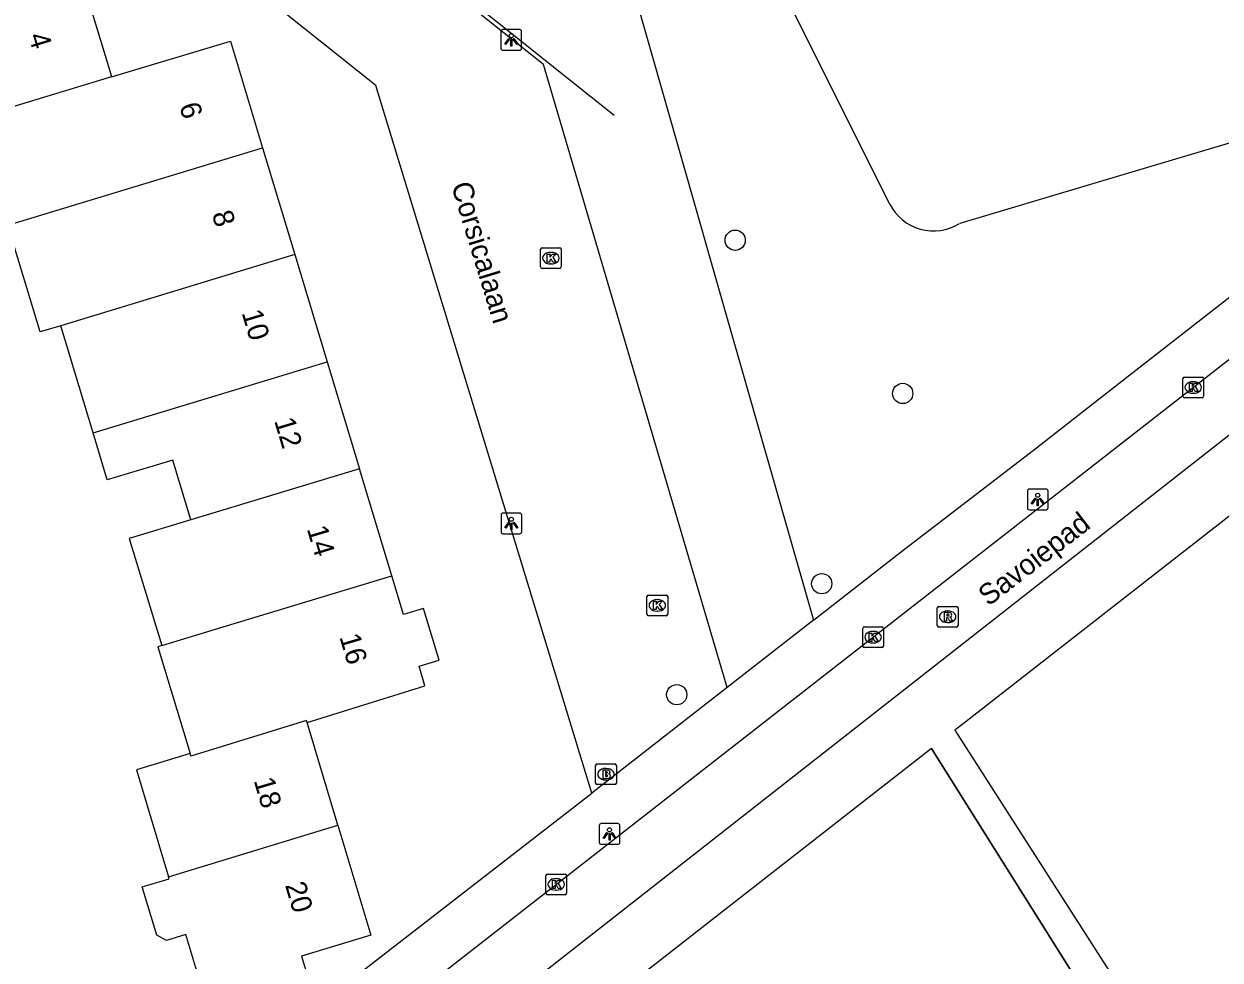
# Model space of a CAD drawing. Extents: x 157767 to 159171, y 387842 to 389425.
# Drawn here: x 158542.4 to 158600.2, y 388420.3 to 388465.6 of the extents above; entities that cross this region are included whole.
import ezdxf

# ---------------------------------------------------------------- set-up
doc = ezdxf.new("R2010")
doc.units = 0
for name, color, linetype in [('IMGEO_Boom', 7, 'Continuous'), ('IMGEO_Brandkraan', 7, 'Continuous'), ('IMGEO_Fietspad_gesloten', 7, 'Continuous'), ('IMGEO_Hek', 7, 'Continuous'), ('IMGEO_Kolk', 7, 'Continuous'), ('IMGEO_Lichtpunt', 7, 'Continuous'), ('IMGEO_Muur', 7, 'Continuous'), ('IMGEO_Openbare_ruimte_label', 7, 'Continuous'), ('IMGEO_Pand', 7, 'Continuous'), ('IMGEO_Pand_nummerreeks', 7, 'Continuous'), ('IMGEO_Parkeervlak_open', 7, 'Continuous'), ('IMGEO_Rijbaan_lokaal_open', 7, 'Continuous'), ('IMGEO_Rioolput', 7, 'Continuous'), ('IMGEO_Voetpad_open', 7, 'Continuous')]:
    doc.layers.add(name, color=color, linetype=linetype)

msp = doc.modelspace()

# ---------------------------------------------------------------- linework, layer by layer
at = {"layer": 'IMGEO_Boom'}
for centre in [(158576.807, 388455.106), (158584.898, 388447.704), (158580.987, 388438.512), (158573.98, 388433.149)]:
    msp.add_circle(centre, 0.489, dxfattribs=at)
at = {"layer": 'IMGEO_Brandkraan'}
for p, q in [((158570.065, 388428.879), (158570.065, 388429.731)), ((158570.14, 388429.805), (158570.992, 388429.805)), ((158571.066, 388429.731), (158571.066, 388428.879)), ((158570.553, 388429.585), (158570.578, 388429.585)), ((158570.992, 388428.805), (158570.14, 388428.805)), ((158570.576, 388429.025), (158570.551, 388429.025))]:
    msp.add_line(p, q, dxfattribs=at)
for points in [[(158570.065, 388428.879), (158570.065, 388429.731)], [(158570.14, 388429.805), (158570.992, 388429.805)], [(158571.066, 388429.731), (158571.066, 388428.879)], [(158570.413, 388429.505), (158570.413, 388429.105), (158570.626, 388429.105)], [(158570.644, 388429.505), (158570.413, 388429.505)], [(158570.592, 388429.424), (158570.538, 388429.424), (158570.538, 388429.348)], [(158570.538, 388429.348), (158570.591, 388429.348)], [(158570.6, 388429.272), (158570.538, 388429.272), (158570.538, 388429.191)], [(158570.538, 388429.191), (158570.6, 388429.191)], [(158570.992, 388428.805), (158570.14, 388428.805)]]:
    msp.add_lwpolyline(points, dxfattribs=at)
for centre, radius, start, end in [((158570.142, 388429.729), 0.0765, 91.55205, 178.44795), ((158570.142, 388429.729), 0.0765, 91.55205, 178.44795), ((158570.99, 388429.729), 0.0765, 1.55205, 88.44795), ((158570.99, 388429.729), 0.0765, 1.55205, 88.44795), ((158570.593, 388429.386), 0.0379, 267.82845, 90.93552), ((158570.601, 388429.231), 0.0404, 269.87594, 90.50774), ((158570.648, 388429.36), 0.145, 59.4692, 91.53667), ((158570.673, 388429.407), 0.0922, 285.51372, 58.15012), ((158570.678, 388429.215), 0.105, 301.31148, 78.98903), ((158570.142, 388428.881), 0.0765, 181.55205, 268.44795), ((158570.142, 388428.881), 0.0765, 181.55205, 268.44795), ((158570.632, 388429.356), 0.251, 268.66757, 293.53466), ((158570.99, 388428.881), 0.0765, 271.55205, 358.44795), ((158570.99, 388428.881), 0.0765, 271.55205, 358.44795)]:
    msp.add_arc(centre, radius, start, end, dxfattribs=at)
for centre, major_axis, ratio, start_param, end_param in [((158570.552, 388429.305), (-0.387, 0.002), 0.722429, 4.712389, 7.853982), ((158570.577, 388429.305), (-0.39, 0.002), 0.717154, 1.570796, 4.712389)]:
    msp.add_ellipse(centre, major_axis=major_axis, ratio=ratio, start_param=start_param, end_param=end_param, dxfattribs=at)
at = {"layer": 'IMGEO_Fietspad_gesloten'}
for points in [[(158612.35, 388454.746), (158604.077, 388448.361), (158556.877, 388411.353), (158545.756, 388402.727), (158544.054, 388401.469), (158540.023, 388398.619), (158533.491, 388394.369), (158520.642, 388386.656)], [(158543.134, 388404.513), (158547.311, 388407.72), (158607.672, 388454.811)]]:
    msp.add_lwpolyline(points, dxfattribs=at)
at = {"layer": 'IMGEO_Hek'}
msp.add_lwpolyline([(158570.958, 388461.13), (158542.949, 388483.478)], dxfattribs=at)
at = {"layer": 'IMGEO_Kolk'}
for p, q in [((158567.404, 388453.814), (158567.404, 388454.666)), ((158567.479, 388454.74), (158568.331, 388454.74)), ((158568.405, 388454.666), (158568.405, 388453.814)), ((158567.892, 388454.52), (158567.917, 388454.52)), ((158568.331, 388453.74), (158567.479, 388453.74)), ((158567.915, 388453.96), (158567.89, 388453.96)), ((158598.433, 388447.566), (158598.433, 388448.418)), ((158598.508, 388448.492), (158599.36, 388448.492)), ((158598.921, 388448.272), (158598.946, 388448.272)), ((158599.434, 388448.418), (158599.434, 388447.566)), ((158598.944, 388447.712), (158598.919, 388447.712)), ((158599.36, 388447.492), (158598.508, 388447.492)), ((158572.545, 388437.037), (158572.545, 388437.889)), ((158572.62, 388437.963), (158573.472, 388437.963)), ((158573.546, 388437.889), (158573.546, 388437.037)), ((158573.033, 388437.743), (158573.058, 388437.743)), ((158573.472, 388436.963), (158572.62, 388436.963)), ((158573.056, 388437.183), (158573.031, 388437.183)), ((158582.965, 388435.5), (158582.965, 388436.352)), ((158583.04, 388436.426), (158583.892, 388436.426)), ((158583.453, 388436.206), (158583.478, 388436.206)), ((158583.966, 388436.352), (158583.966, 388435.5)), ((158583.476, 388435.646), (158583.451, 388435.646)), ((158583.892, 388435.426), (158583.04, 388435.426)), ((158567.662, 388423.559), (158567.662, 388424.411)), ((158567.737, 388424.485), (158568.589, 388424.485)), ((158568.15, 388424.265), (158568.175, 388424.265)), ((158568.663, 388424.411), (158568.663, 388423.559)), ((158568.589, 388423.485), (158567.737, 388423.485)), ((158568.173, 388423.705), (158568.148, 388423.705))]:
    msp.add_line(p, q, dxfattribs=at)
for points in [[(158567.404, 388453.814), (158567.404, 388454.666)], [(158567.479, 388454.74), (158568.331, 388454.74)], [(158568.405, 388454.666), (158568.405, 388453.814)], [(158567.725, 388454.44), (158567.848, 388454.44), (158567.848, 388454.289), (158567.978, 388454.44), (158568.142, 388454.44), (158567.996, 388454.289), (158568.149, 388454.04), (158567.997, 388454.04), (158567.912, 388454.204), (158567.848, 388454.137), (158567.848, 388454.04), (158567.725, 388454.04), (158567.725, 388454.44)], [(158568.331, 388453.74), (158567.479, 388453.74)], [(158598.433, 388447.566), (158598.433, 388448.418)], [(158598.508, 388448.492), (158599.36, 388448.492)], [(158599.434, 388448.418), (158599.434, 388447.566)], [(158598.754, 388448.192), (158598.877, 388448.192), (158598.877, 388448.041), (158599.007, 388448.192), (158599.171, 388448.192), (158599.025, 388448.041), (158599.178, 388447.792), (158599.026, 388447.792), (158598.941, 388447.956), (158598.877, 388447.889), (158598.877, 388447.792), (158598.754, 388447.792), (158598.754, 388448.192)], [(158599.36, 388447.492), (158598.508, 388447.492)], [(158572.545, 388437.037), (158572.545, 388437.889)], [(158572.62, 388437.963), (158573.472, 388437.963)], [(158573.546, 388437.889), (158573.546, 388437.037)], [(158572.866, 388437.663), (158572.989, 388437.663), (158572.989, 388437.512), (158573.119, 388437.663), (158573.283, 388437.663), (158573.137, 388437.512), (158573.29, 388437.263), (158573.138, 388437.263), (158573.053, 388437.427), (158572.989, 388437.36), (158572.989, 388437.263), (158572.866, 388437.263), (158572.866, 388437.663)], [(158573.472, 388436.963), (158572.62, 388436.963)], [(158582.965, 388435.5), (158582.965, 388436.352)], [(158583.04, 388436.426), (158583.892, 388436.426)], [(158583.286, 388436.126), (158583.409, 388436.126), (158583.409, 388435.975), (158583.539, 388436.126), (158583.703, 388436.126), (158583.557, 388435.975), (158583.71, 388435.726), (158583.558, 388435.726), (158583.473, 388435.89), (158583.409, 388435.823), (158583.409, 388435.726), (158583.286, 388435.726), (158583.286, 388436.126)], [(158583.966, 388436.352), (158583.966, 388435.5)], [(158583.892, 388435.426), (158583.04, 388435.426)], [(158567.662, 388423.559), (158567.662, 388424.411)], [(158567.737, 388424.485), (158568.589, 388424.485)], [(158567.983, 388424.185), (158568.106, 388424.185), (158568.106, 388424.034), (158568.236, 388424.185), (158568.4, 388424.185), (158568.254, 388424.034), (158568.407, 388423.785), (158568.255, 388423.785), (158568.17, 388423.949), (158568.106, 388423.882), (158568.106, 388423.785), (158567.983, 388423.785), (158567.983, 388424.185)], [(158568.663, 388424.411), (158568.663, 388423.559)], [(158568.589, 388423.485), (158567.737, 388423.485)]]:
    msp.add_lwpolyline(points, dxfattribs=at)
for centre, start, end in [((158567.481, 388454.664), 91.55205, 178.44795), ((158567.481, 388454.664), 91.55205, 178.44795), ((158568.329, 388454.664), 1.55205, 88.44795), ((158568.329, 388454.664), 1.55205, 88.44795), ((158567.481, 388453.816), 181.55205, 268.44795), ((158567.481, 388453.816), 181.55205, 268.44795), ((158568.329, 388453.816), 271.55205, 358.44795), ((158568.329, 388453.816), 271.55205, 358.44795), ((158598.51, 388448.416), 91.55205, 178.44795), ((158598.51, 388448.416), 91.55205, 178.44795), ((158599.358, 388448.416), 1.55205, 88.44795), ((158599.358, 388448.416), 1.55205, 88.44795), ((158598.51, 388447.568), 181.55205, 268.44795), ((158598.51, 388447.568), 181.55205, 268.44795), ((158599.358, 388447.568), 271.55205, 358.44795), ((158599.358, 388447.568), 271.55205, 358.44795), ((158572.622, 388437.887), 91.55205, 178.44795), ((158572.622, 388437.887), 91.55205, 178.44795), ((158573.47, 388437.887), 1.55205, 88.44795), ((158573.47, 388437.887), 1.55205, 88.44795), ((158572.622, 388437.039), 181.55205, 268.44795), ((158572.622, 388437.039), 181.55205, 268.44795), ((158573.47, 388437.039), 271.55205, 358.44795), ((158573.47, 388437.039), 271.55205, 358.44795), ((158583.042, 388436.35), 91.55205, 178.44795), ((158583.042, 388436.35), 91.55205, 178.44795), ((158583.89, 388436.35), 1.55205, 88.44795), ((158583.89, 388436.35), 1.55205, 88.44795), ((158583.042, 388435.502), 181.55205, 268.44795), ((158583.042, 388435.502), 181.55205, 268.44795), ((158583.89, 388435.502), 271.55205, 358.44795), ((158583.89, 388435.502), 271.55205, 358.44795), ((158567.739, 388424.409), 91.55205, 178.44795), ((158567.739, 388424.409), 91.55205, 178.44795), ((158568.587, 388424.409), 1.55205, 88.44795), ((158568.587, 388424.409), 1.55205, 88.44795), ((158567.739, 388423.561), 181.55205, 268.44795), ((158567.739, 388423.561), 181.55205, 268.44795), ((158568.587, 388423.561), 271.55205, 358.44795), ((158568.587, 388423.561), 271.55205, 358.44795)]:
    msp.add_arc(centre, 0.0765, start, end, dxfattribs=at)
for centre, major_axis, ratio, start_param, end_param in [((158567.891, 388454.24), (-0.387, 0.002), 0.722429, 4.712389, 7.853982), ((158567.916, 388454.24), (-0.39, 0.002), 0.717154, 1.570796, 4.712389), ((158598.92, 388447.992), (-0.387, 0.002), 0.722429, 4.712389, 7.853982), ((158598.945, 388447.992), (-0.39, 0.002), 0.717154, 1.570796, 4.712389), ((158573.032, 388437.463), (-0.387, 0.002), 0.722429, 4.712389, 7.853982), ((158573.057, 388437.463), (-0.39, 0.002), 0.717154, 1.570796, 4.712389), ((158583.452, 388435.926), (-0.387, 0.002), 0.722429, 4.712389, 7.853982), ((158583.477, 388435.926), (-0.39, 0.002), 0.717154, 1.570796, 4.712389), ((158568.149, 388423.985), (-0.387, 0.002), 0.722429, 4.712389, 7.853982), ((158568.174, 388423.985), (-0.39, 0.002), 0.717154, 1.570796, 4.712389)]:
    msp.add_ellipse(centre, major_axis=major_axis, ratio=ratio, start_param=start_param, end_param=end_param, dxfattribs=at)
at = {"layer": 'IMGEO_Lichtpunt'}
for p, q in [((158565.493, 388465.186), (158565.493, 388464.379)), ((158565.493, 388465.186), (158565.493, 388464.379)), ((158566.395, 388465.281), (158565.587, 388465.281)), ((158566.395, 388465.281), (158565.587, 388465.281)), ((158566.489, 388464.379), (158566.489, 388465.186)), ((158566.489, 388464.379), (158566.489, 388465.186)), ((158565.587, 388464.285), (158566.395, 388464.285)), ((158565.587, 388464.285), (158566.395, 388464.285)), ((158591.824, 388443.082), (158591.016, 388443.082)), ((158591.824, 388443.082), (158591.016, 388443.082)), ((158590.922, 388442.987), (158590.922, 388442.18)), ((158590.922, 388442.987), (158590.922, 388442.18)), ((158591.918, 388442.18), (158591.918, 388442.987)), ((158591.918, 388442.18), (158591.918, 388442.987)), ((158566.398, 388441.921), (158565.59, 388441.921)), ((158566.398, 388441.921), (158565.59, 388441.921)), ((158591.016, 388442.086), (158591.824, 388442.086)), ((158591.016, 388442.086), (158591.824, 388442.086)), ((158565.496, 388441.826), (158565.496, 388441.019)), ((158565.496, 388441.826), (158565.496, 388441.019)), ((158566.492, 388441.019), (158566.492, 388441.826)), ((158566.492, 388441.019), (158566.492, 388441.826)), ((158565.59, 388440.925), (158566.398, 388440.925)), ((158565.59, 388440.925), (158566.398, 388440.925)), ((158571.139, 388426.918), (158570.331, 388426.918)), ((158571.139, 388426.918), (158570.331, 388426.918)), ((158570.237, 388426.823), (158570.237, 388426.016)), ((158570.237, 388426.823), (158570.237, 388426.016)), ((158571.233, 388426.016), (158571.233, 388426.823)), ((158571.233, 388426.016), (158571.233, 388426.823)), ((158570.331, 388425.922), (158571.139, 388425.922)), ((158570.331, 388425.922), (158571.139, 388425.922))]:
    msp.add_line(p, q, dxfattribs=at)
for points in [[(158565.867, 388464.85), (158565.906, 388464.822), (158565.718, 388464.56), (158565.68, 388464.587), (158565.867, 388464.85)], [(158565.969, 388464.802), (158566.016, 388464.802), (158566.016, 388464.48), (158565.969, 388464.48), (158565.969, 388464.802)], [(158566.079, 388464.822), (158566.117, 388464.849), (158566.304, 388464.587), (158566.265, 388464.559), (158566.079, 388464.822)], [(158591.296, 388442.651), (158591.335, 388442.623), (158591.147, 388442.361), (158591.109, 388442.388), (158591.296, 388442.651)], [(158591.398, 388442.603), (158591.445, 388442.603), (158591.445, 388442.281), (158591.398, 388442.281), (158591.398, 388442.603)], [(158591.508, 388442.623), (158591.546, 388442.65), (158591.733, 388442.388), (158591.694, 388442.36), (158591.508, 388442.623)], [(158565.87, 388441.49), (158565.909, 388441.462), (158565.721, 388441.2), (158565.683, 388441.227), (158565.87, 388441.49)], [(158565.972, 388441.442), (158566.019, 388441.442), (158566.019, 388441.12), (158565.972, 388441.12), (158565.972, 388441.442)], [(158566.082, 388441.462), (158566.12, 388441.489), (158566.307, 388441.227), (158566.268, 388441.199), (158566.082, 388441.462)], [(158570.611, 388426.487), (158570.65, 388426.459), (158570.462, 388426.197), (158570.424, 388426.224), (158570.611, 388426.487)], [(158570.713, 388426.439), (158570.76, 388426.439), (158570.76, 388426.117), (158570.713, 388426.117), (158570.713, 388426.439)], [(158570.823, 388426.459), (158570.861, 388426.486), (158571.048, 388426.224), (158571.009, 388426.196), (158570.823, 388426.459)]]:
    msp.add_lwpolyline(points, dxfattribs=at)
for centre in [(158565.992, 388464.984), (158591.421, 388442.785), (158565.995, 388441.624), (158570.736, 388426.621)]:
    msp.add_circle(centre, 0.0994, dxfattribs=at)
for centre, start, end in [((158565.587, 388465.186), 90, 180), ((158565.587, 388465.186), 90, 180), ((158566.395, 388465.186), 0, 90), ((158566.395, 388465.186), 0, 90), ((158565.587, 388464.379), 180, 270), ((158565.587, 388464.379), 180, 270), ((158566.395, 388464.379), 270, 0), ((158566.395, 388464.379), 270, 360), ((158591.016, 388442.987), 90, 180), ((158591.016, 388442.987), 90, 180), ((158591.824, 388442.987), 0, 90), ((158591.824, 388442.987), 0, 90), ((158565.59, 388441.826), 90, 180), ((158565.59, 388441.826), 90, 180), ((158566.398, 388441.826), 0, 90), ((158566.398, 388441.826), 0, 90), ((158591.016, 388442.18), 180, 270), ((158591.016, 388442.18), 180, 270), ((158591.824, 388442.18), 270, 0), ((158591.824, 388442.18), 270, 360), ((158565.59, 388441.019), 180, 270), ((158565.59, 388441.019), 180, 270), ((158566.398, 388441.019), 270, 0), ((158566.398, 388441.019), 270, 360), ((158570.331, 388426.823), 90, 180), ((158570.331, 388426.823), 90, 180), ((158571.139, 388426.823), 0, 90), ((158571.139, 388426.823), 0, 90), ((158570.331, 388426.016), 180, 270), ((158570.331, 388426.016), 180, 270), ((158571.139, 388426.016), 270, 0), ((158571.139, 388426.016), 270, 360)]:
    msp.add_arc(centre, 0.0946, start, end, dxfattribs=at)
at = {"layer": 'IMGEO_Muur'}
msp.add_lwpolyline([(158586.296, 388430.551), (158593.331, 388419.346)], dxfattribs=at)
at = {"layer": 'IMGEO_Pand'}
for points in [[(158545.118, 388468.163), (158546.467, 388463.708), (158546.629, 388463.171), (158546.683, 388462.994)], [(158584.259, 388456.87), (158578.574, 388468.268)], [(158546.683, 388462.994), (158552.424, 388464.727), (158553.979, 388459.57)], [(158546.683, 388462.994), (158540.626, 388461.165)], [(158601.053, 388459.907), (158595.532, 388458.265), (158587.65, 388455.917)], [(158541.667, 388455.832), (158553.979, 388459.57)], [(158553.979, 388459.57), (158555.536, 388454.411)], [(158544.227, 388450.972), (158543.237, 388450.673), (158541.667, 388455.832)], [(158555.536, 388454.411), (158544.227, 388450.972)], [(158555.536, 388454.411), (158557.1, 388449.223)], [(158545.788, 388445.805), (158544.227, 388450.972)], [(158545.788, 388445.805), (158557.1, 388449.223)], [(158557.1, 388449.223), (158558.659, 388444.055)], [(158550.512, 388441.592), (158549.639, 388444.483), (158546.476, 388443.527), (158545.788, 388445.805)], [(158558.659, 388444.055), (158550.512, 388441.592)], [(158560.218, 388438.886), (158558.659, 388444.055)], [(158550.512, 388441.592), (158547.539, 388440.693), (158549.102, 388435.526)], [(158549.102, 388435.526), (158552.073, 388436.423), (158560.218, 388438.886)], [(158556.125, 388431.811), (158561.819, 388433.58), (158561.533, 388434.528), (158562.501, 388434.82), (158561.75, 388437.31), (158560.782, 388437.018), (158560.218, 388438.886)], [(158549.102, 388435.526), (158548.91, 388435.468), (158550.471, 388430.3)], [(158556.125, 388431.811), (158556.096, 388431.907), (158550.51, 388430.171), (158550.471, 388430.3)], [(158557.613, 388426.84), (158556.125, 388431.811)], [(158550.471, 388430.3), (158547.879, 388429.519), (158549.432, 388424.35)], [(158557.613, 388426.84), (158559.2, 388421.536), (158555.853, 388420.514), (158556.572, 388418.162), (158551.039, 388413.875), (158549.75, 388418.093), (158550.296, 388419.118), (158550.945, 388419.313), (158550.271, 388421.558), (158549.334, 388421.277), (158548.861, 388421.531), (158548.161, 388423.859), (158549.462, 388424.25), (158549.432, 388424.35)], [(158549.432, 388424.35), (158557.613, 388426.84)]]:
    msp.add_lwpolyline(points, dxfattribs=at)
msp.add_arc((158586.387, 388457.934), 2.379, 206.55531, 302.04992, dxfattribs=at)
at = {"layer": 'IMGEO_Parkeervlak_open'}
msp.add_lwpolyline([(158546.841, 388486.547), (158572.12, 388466.385), (158574.41, 388458.376), (158576.104, 388452.449), (158580.59, 388436.753)], dxfattribs=at)
at = {"layer": 'IMGEO_Rijbaan_lokaal_open'}
for points in [[(158576.416, 388433.493), (158567.552, 388463.6), (158543.277, 388482.921)], [(158569.875, 388428.384), (158559.44, 388462.588), (158538.567, 388479.214)], [(158576.416, 388433.493), (158569.875, 388428.384)]]:
    msp.add_lwpolyline(points, dxfattribs=at)
at = {"layer": 'IMGEO_Rioolput'}
for p, q in [((158586.57, 388436.489), (158586.57, 388437.341)), ((158586.645, 388437.415), (158587.497, 388437.415)), ((158587.571, 388437.341), (158587.571, 388436.489)), ((158587.058, 388437.195), (158587.083, 388437.195)), ((158587.497, 388436.415), (158586.645, 388436.415)), ((158587.081, 388436.635), (158587.056, 388436.635))]:
    msp.add_line(p, q, dxfattribs=at)
for points in [[(158586.57, 388436.489), (158586.57, 388437.341)], [(158586.645, 388437.415), (158587.497, 388437.415)], [(158587.571, 388437.341), (158587.571, 388436.489)], [(158587.159, 388437.113), (158586.907, 388437.115), (158586.907, 388436.715)], [(158586.907, 388436.715), (158587.031, 388436.715), (158587.031, 388436.877), (158587.042, 388436.877)], [(158587.085, 388437.034), (158587.031, 388437.034), (158587.031, 388436.953)], [(158587.031, 388436.953), (158587.083, 388436.953)], [(158587.089, 388436.848), (158587.16, 388436.715), (158587.3, 388436.715), (158587.235, 388436.841)], [(158587.497, 388436.415), (158586.645, 388436.415)]]:
    msp.add_lwpolyline(points, dxfattribs=at)
for centre, radius, start, end in [((158586.647, 388437.339), 0.0765, 91.55205, 178.44795), ((158586.647, 388437.339), 0.0765, 91.55205, 178.44795), ((158587.495, 388437.339), 0.0765, 1.55205, 88.44795), ((158587.495, 388437.339), 0.0765, 1.55205, 88.44795), ((158587.041, 388436.824), 0.0533, 26.02933, 88.69889), ((158587.067, 388437.142), 0.19, 274.7715, 282.96867), ((158587.091, 388436.938), 0.0964, 77.00612, 93.18647), ((158587.105, 388436.995), 0.0378, 276.66336, 79.67722), ((158587.158, 388437.003), 0.109, 350.36119, 89.41601), ((158587.156, 388437.003), 0.112, 277.58423, 350.98172), ((158587.14, 388436.788), 0.108, 29.51342, 73.79051), ((158586.647, 388436.491), 0.0765, 181.55205, 268.44795), ((158586.647, 388436.491), 0.0765, 181.55205, 268.44795), ((158587.495, 388436.491), 0.0765, 271.55205, 358.44795), ((158587.495, 388436.491), 0.0765, 271.55205, 358.44795)]:
    msp.add_arc(centre, radius, start, end, dxfattribs=at)
for centre, major_axis, ratio, start_param, end_param in [((158587.057, 388436.915), (-0.387, 0.002), 0.722429, 4.712389, 7.853982), ((158587.082, 388436.915), (-0.39, 0.002), 0.717154, 1.570796, 4.712389)]:
    msp.add_ellipse(centre, major_axis=major_axis, ratio=ratio, start_param=start_param, end_param=end_param, dxfattribs=at)
at = {"layer": 'IMGEO_Voetpad_open'}
for points in [[(158580.59, 388436.753), (158584.771, 388440.019), (158591.218, 388444.966), (158595.873, 388448.598), (158597.911, 388450.189), (158613.32, 388462.213), (158618.4, 388466.48), (158623.335, 388470.914), (158629.613, 388477.098), (158631.562, 388479.175), (158640.35, 388488.498)], [(158629.121, 388464.777), (158625.579, 388461.577), (158618.904, 388456.008), (158587.816, 388431.738), (158587.422, 388431.43), (158593.275, 388422.284), (158601.024, 388410.197)], [(158580.59, 388436.753), (158576.416, 388433.493)], [(158593.331, 388419.346), (158586.296, 388430.551), (158555.065, 388406.169)], [(158548.773, 388412.037), (158551.056, 388413.805), (158569.875, 388428.384)]]:
    msp.add_lwpolyline(points, dxfattribs=at)

# ---------------------------------------------------------------- texts
at = {"layer": 'IMGEO_Openbare_ruimte_label'}
for s, rotation, p in [('Corsicalaan', 286.98473, (158563.079, 388457.757)), ('Savoiepad', 37.60354, (158589.038, 388437.393))]:
    msp.add_text(s, height=1, rotation=rotation, dxfattribs=at).set_placement(p)
at = {"layer": 'IMGEO_Pand_nummerreeks'}
for s, rotation, p in [('4', 286.85048, (158542.655, 388464.979)), ('6', 286.78745, (158549.942, 388461.599)), ('8', 286.78549, (158551.517, 388456.377)), ('10', 286.78549, (158552.958, 388451.6)), ('12', 286.78549, (158554.53, 388446.386)), ('14', 286.78745, (158556.105, 388441.165)), ('16', 286.78745, (158557.679, 388435.946)), ('18', 286.6614, (158553.541, 388429.004)), ('20', 286.66087, (158555.053, 388423.953))]:
    msp.add_text(s, height=1, rotation=rotation, dxfattribs=at).set_placement(p)

doc.saveas('drawing.dxf')
